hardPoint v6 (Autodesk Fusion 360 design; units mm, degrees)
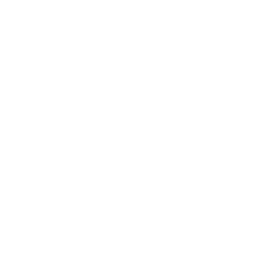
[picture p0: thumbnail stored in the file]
parameter "diskHeight" = 40
parameter "diskCutDepth" = 20
parameter "sinkDepthTube" = 15
parameter "maxMillingDepth" = 20
parameter "drillDiameter" = 5
parameter "tubeWidth" = 50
